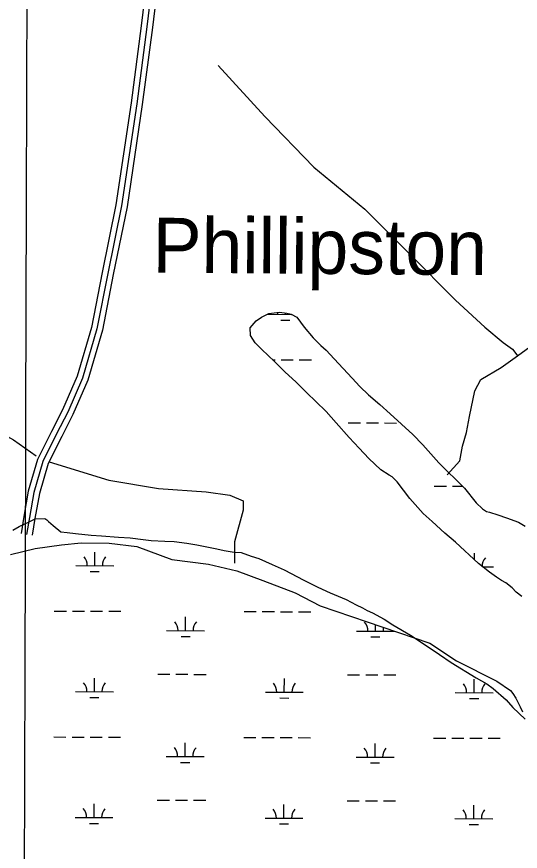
# Model space of a CAD drawing. Extents: x 3161665 to 3199565, y 885729 to 911164.
# Drawn here: x 3171102 to 3172433, y 897608 to 899813 of the extents above; entities that cross this region are included whole.
import ezdxf

# ---------------------------------------------------------------- set-up
doc = ezdxf.new("R2010")
doc.units = 0
for name, color, linetype in [('V-GRID-MAJR', 7, 'Continuous'), ('V-ROAD-CNTR', 7, 'Continuous'), ('V-SITE-VEGE', 7, 'Continuous'), ('V-TOPO-GNAM-IDEN', 7, 'Continuous'), ('V-TOPO-SHOR', 7, 'Continuous'), ('V-WETL-SWMP', 7, 'Continuous')]:
    doc.layers.add(name, color=color, linetype=linetype)

msp = doc.modelspace()

# ---------------------------------------------------------------- linework, layer by layer
at = {"layer": 'V-GRID-MAJR'}
msp.add_spline([(3171102.7, 891181.041), (3171121.2120000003, 897241.873), (3171139.73, 903304.649), (3171158.249, 909367.4720000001), (3171158.255, 909369.371)], degree=3, dxfattribs=at)
at = {"layer": 'V-ROAD-CNTR'}
for points in [[(3171451.753059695, 899962.9710463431), (3171430.6191019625, 899788.0113962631), (3171403.865155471, 899584.6108030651), (3171363.623235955, 899315.424341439), (3171327.398308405, 899136.9486983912), (3171298.884365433, 898991.522989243), (3171261.028441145, 898862.6312470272), (3171222.8165175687, 898774.211423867), (3171193.670575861, 898717.0455381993), (3171156.653649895, 898642.876686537), (3171132.1736988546, 898559.4978532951), (3171120.244722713, 898491.8829885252), (3171113.095737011, 898447.3320776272)], [(3171466.662029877, 899961.3150496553), (3171445.501072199, 899786.1334000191), (3171418.720125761, 899582.523807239), (3171378.401206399, 899312.8213466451), (3171342.108278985, 899134.013704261), (3171313.471336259, 898987.958996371), (3171275.161412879, 898857.5232572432), (3171236.396490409, 898767.8234366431), (3171207.063549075, 898710.2895517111), (3171170.670621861, 898637.3716975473), (3171146.8006696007, 898556.071860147), (3171135.0366931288, 898489.3919935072), (3171127.906707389, 898444.9560823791)], [(3171481.5710000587, 899959.6590529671), (3171460.3830424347, 899784.2554037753), (3171433.5750960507, 899580.436811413), (3171393.179176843, 899310.218351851), (3171356.8182495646, 899131.0787101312), (3171328.0583070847, 898984.395003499), (3171289.2943846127, 898852.4152674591), (3171249.976463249, 898761.4354494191), (3171220.4565222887, 898703.5335652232), (3171184.687593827, 898631.8667085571), (3171161.427640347, 898552.6458669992), (3171149.8286635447, 898486.9009984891), (3171142.717677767, 898442.580087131)]]:
    msp.add_lwpolyline(points, dxfattribs=at)
at = {"layer": 'V-SITE-VEGE'}
msp.add_lwpolyline([(3171091.5900000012, 898456.6059999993), (3171108.480000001, 898466.0019999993), (3171134.598000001, 898478.5609999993), (3171149.958000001, 898486.3959999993), (3171176.181000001, 898486.6129999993), (3171180.834000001, 898483.5699999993), (3171185.497000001, 898478.9779999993), (3171197.926000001, 898468.2839999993), (3171218.120000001, 898451.4839999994), (3171235.098000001, 898450.0789999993), (3171256.716000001, 898447.1749999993), (3171298.399000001, 898442.8949999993), (3171326.176000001, 898441.5799999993), (3171370.945000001, 898437.3219999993), (3171401.807000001, 898436.0359999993), (3171435.777000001, 898431.6899999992), (3171457.396000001, 898428.7839999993), (3171492.883000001, 898427.5349999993), (3171517.576000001, 898426.1969999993), (3171551.546000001, 898421.8489999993), (3171577.806000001, 898417.4399999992), (3171608.706000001, 898411.5249999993), (3171630.337000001, 898407.0769999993), (3171650.4280000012, 898402.6169999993), (3171676.687000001, 898398.2049999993), (3171695.207000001, 898396.8169999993), (3171721.508000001, 898387.7789999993), (3171741.609000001, 898381.7739999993), (3171777.224000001, 898365.1009999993), (3171808.187000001, 898351.4759999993), (3171860.856000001, 898324.1449999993), (3171898.029000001, 898305.9449999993), (3171930.549000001, 898290.7879999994), (3171972.347000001, 898272.6239999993), (3171998.682000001, 898258.9619999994), (3172015.711000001, 898251.3839999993), (3172028.116000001, 898243.7779999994), (3172042.048000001, 898237.7239999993), (3172073.037000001, 898221.0099999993), (3172096.300000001, 898205.7789999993), (3172142.802000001, 898178.3979999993), (3172173.817000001, 898158.6019999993), (3172218.801000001, 898128.1229999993), (3172249.828000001, 898106.7869999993), (3172316.497000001, 898065.6899999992), (3172344.386000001, 898050.4959999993), (3172361.457000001, 898038.2959999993), (3172395.6440000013, 898007.7289999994), (3172412.775000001, 897987.8189999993), (3172445.423000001, 897957.2379999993)], dxfattribs=at)
at = {"layer": 'V-TOPO-SHOR'}
for points in [[(3171633.7276054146, 899683.8705969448), (3171757.827883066, 899548.5373845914), (3171887.263373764, 899414.9695555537), (3172022.080953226, 899304.4923367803), (3172139.1118849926, 899186.9457721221), (3172261.4624045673, 899064.0561817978), (3172339.4986509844, 898992.8002143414), (3172387.3905664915, 898951.8213923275), (3172412.2309348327, 898933.995681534), (3172426.4086897, 898916.1934085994)], [(3172239.121537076, 898602.0564736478), (3172272.9685122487, 898639.3014009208), (3172280.1628600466, 898678.3820250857), (3172290.903599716, 898713.90063214), (3172298.1057601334, 898756.5354607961), (3172312.47101787, 898824.0340956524), (3172328.5313453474, 898854.2096770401), (3172381.9147262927, 898886.0803281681), (3172406.8332208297, 898903.7966622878), (3172419.2924680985, 898912.6548293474), (3172454.8892013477, 898937.4561345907), (3172485.150721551, 898960.4920565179), (3172510.069216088, 898978.2083906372), (3172542.0883069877, 898992.3548950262), (3172575.8805938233, 899004.7203908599), (3172595.4482500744, 899013.5629326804), (3172615.0159063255, 899022.405474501), (3172615.0159063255, 899022.405474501)], [(3170261.761000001, 898924.8649999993), (3170329.4202272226, 898917.248649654), (3170444.8889037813, 898897.446614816), (3170535.4781489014, 898877.6992683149), (3170690.019637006, 898847.1486811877), (3170823.212460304, 898805.9823563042), (3170917.332472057, 898775.5645837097), (3171030.9654517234, 898729.109921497), (3171093.089810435, 898695.2082579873), (3171153.4175353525, 898652.4249895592)], [(3171187.147321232, 898636.3568494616), (3171345.203950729, 898588.0274272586), (3171476.6626411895, 898566.4131333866), (3171602.8173690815, 898557.2502741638), (3171664.99641613, 898548.2280420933), (3171700.507210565, 898533.9330979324), (3171700.452522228, 898509.0536664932), (3171677.166596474, 898425.5806429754), (3171677.0415945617, 898368.7133711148)]]:
    msp.add_lwpolyline(points, dxfattribs=at)
at = {"layer": 'V-WETL-SWMP'}
for p, q in [((3171763.920245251, 899026.4123794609), (3171828.2566643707, 899026.234588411)), ((3171811.712233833, 899026.280308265), (3171811.7231690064, 899030.2373684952)), ((3171799.669636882, 899010.8825285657), (3171823.6695452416, 899010.8162058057)), ((3171777.977275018, 898906.3020749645), (3171784.536526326, 898906.2839487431)), ((3171800.5364652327, 898906.2397335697), (3171832.536343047, 898906.1513032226)), ((3171848.5362819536, 898906.1070880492), (3171880.536159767, 898906.0186577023)), ((3171977.984572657, 898739.5747285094), (3172009.9844504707, 898739.4862981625)), ((3172025.984389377, 898739.4420829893), (3172057.98426719, 898739.353652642)), ((3172073.9842060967, 898739.3094374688), (3172105.9840839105, 898739.2210071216)), ((3172205.523585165, 898572.444298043), (3172237.5234629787, 898572.3558676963)), ((3172253.5234018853, 898572.3116525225), (3172280.083977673, 898572.2382534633)), ((3171307.971383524, 898362.3200874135), (3171308.0708592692, 898398.319946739)), ((3172311.829225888, 898377.4831044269), (3172311.879141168, 898395.545714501)), ((3171257.9715819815, 898362.4582598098), (3171357.9711850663, 898362.181915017)), ((3172332.8352927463, 898359.4876655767), (3172361.779466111, 898359.4076795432)), ((3171295.9287919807, 898346.9223090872), (3171319.928696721, 898346.8559863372)), ((3171200.7960255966, 898242.5448144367), (3171232.795898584, 898242.456384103)), ((3171248.7958350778, 898242.4121689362), (3171280.795708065, 898242.3237386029)), ((3171296.7956445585, 898242.2795234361), (3171328.7955175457, 898242.1910931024)), ((3171344.7954540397, 898242.1468779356), (3171376.7953270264, 898242.0584476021)), ((3171547.970435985, 898190.8432230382), (3171548.0699117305, 898226.8430823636)), ((3171702.7020334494, 898241.1578178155), (3171734.701906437, 898241.0693874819)), ((3171750.70184293, 898241.0251723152), (3171782.701715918, 898240.9367419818)), ((3171798.7016524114, 898240.892526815), (3171830.7015253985, 898240.8040964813)), ((3171846.701461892, 898240.7598813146), (3171878.7013348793, 898240.6714509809)), ((3172049.8764438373, 898189.4562264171), (3172049.923488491, 898206.481491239)), ((3171497.9706344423, 898190.9813954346), (3171597.970237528, 898190.705050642)), ((3171999.876642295, 898189.5943988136), (3172099.8762453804, 898189.3180540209)), ((3171535.9278444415, 898175.4454447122), (3171559.9277491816, 898175.3791219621)), ((3172037.833852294, 898174.058448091), (3172061.8337570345, 898173.992125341)), ((3171474.2437639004, 898075.6145332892), (3171506.243636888, 898075.5261029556)), ((3171522.2435733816, 898075.4818877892), (3171554.2434463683, 898075.3934574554)), ((3171570.2433828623, 898075.3492422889), (3171602.2432558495, 898075.260811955)), ((3171976.1497717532, 898074.2275366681), (3172008.149644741, 898074.1391063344)), ((3172024.149581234, 898074.0948911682), (3172056.149454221, 898074.0064608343)), ((3172072.1493907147, 898073.9622456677), (3172104.149263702, 898073.8738153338)), ((3171307.052130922, 898029.6463873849), (3171307.1516066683, 898065.6462467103)), ((3171808.9581387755, 898028.2593907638), (3171809.057614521, 898064.2592500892)), ((3172310.864146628, 898026.8723941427), (3172310.9636223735, 898062.872253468)), ((3171257.05232938, 898029.7845597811), (3171357.0519324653, 898029.5082149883)), ((3171758.958337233, 898028.3975631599), (3171858.957940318, 898028.1212183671)), ((3171295.0095393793, 898014.2486090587), (3171319.0094441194, 898014.1822863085)), ((3171796.915547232, 898012.8616124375), (3171820.9154519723, 898012.7952896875)), ((3172260.864345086, 898027.0105665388), (3172360.8639481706, 898026.734221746)), ((3172298.8215550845, 898011.4746158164), (3172322.821459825, 898011.4082930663)), ((3171199.8767729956, 897909.871114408), (3171231.8766459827, 897909.7826840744)), ((3171247.876582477, 897909.7384689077), (3171279.876455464, 897909.6500385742)), ((3171295.8763919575, 897909.6058234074), (3171327.8762649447, 897909.5173930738)), ((3171343.8762014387, 897909.473177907), (3171375.876074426, 897909.3847475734)), ((3171701.7827808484, 897908.4841177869), (3171733.782653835, 897908.3956874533)), ((3171749.782590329, 897908.3514722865), (3171781.7824633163, 897908.2630419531)), ((3171797.78239981, 897908.2188267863), (3171829.7822727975, 897908.1303964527)), ((3171845.782209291, 897908.0861812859), (3171877.7820822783, 897907.9977509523)), ((3172203.6887887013, 897907.0971211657), (3172235.6886616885, 897907.0086908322)), ((3172251.6885981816, 897906.9644756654), (3172283.688471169, 897906.8760453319)), ((3172299.688407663, 897906.8318301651), (3172331.6882806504, 897906.7433998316)), ((3172347.6882171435, 897906.6991846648), (3172379.6880901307, 897906.6107543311)), ((3171547.0511833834, 897858.1695230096), (3171547.150659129, 897894.1693823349)), ((3172048.957191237, 897856.7825263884), (3172049.056666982, 897892.7823857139)), ((3171497.051381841, 897858.307695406), (3171597.0509849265, 897858.0313506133)), ((3171998.9573896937, 897856.9206987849), (3172098.9569927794, 897856.6443539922)), ((3171535.0085918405, 897842.7717446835), (3171559.0084965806, 897842.7054219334)), ((3172036.9145996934, 897841.3847480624), (3172060.914504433, 897841.3184253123)), ((3171473.3245112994, 897742.9408332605), (3171505.324384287, 897742.8524029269)), ((3171521.32432078, 897742.8081877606), (3171553.3241937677, 897742.7197574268)), ((3171569.324130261, 897742.6755422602), (3171601.3240032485, 897742.5871119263)), ((3171975.2305191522, 897741.5538366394), (3172007.2303921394, 897741.4654063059)), ((3172023.230328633, 897741.4211911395), (3172055.23020162, 897741.3327608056)), ((3172071.230138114, 897741.288545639), (3172103.230011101, 897741.2001153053)), ((3171306.1328783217, 897696.9726873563), (3171306.232354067, 897732.9725466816)), ((3171808.038886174, 897695.5856907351), (3171808.13836192, 897731.5855500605)), ((3172309.944894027, 897694.198694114), (3172310.0443697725, 897730.1985534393)), ((3171256.1330767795, 897697.1108597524), (3171356.132679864, 897696.8345149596)), ((3171294.0902867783, 897681.57490903), (3171318.090191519, 897681.5085862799)), ((3171758.039084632, 897695.7238631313), (3171858.038687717, 897695.4475183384)), ((3171795.996294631, 897680.1879124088), (3171819.9961993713, 897680.1215896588)), ((3172259.9450924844, 897694.3368665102), (3172359.9446955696, 897694.0605217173)), ((3172297.9023024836, 897678.8009157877), (3172321.902207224, 897678.7345930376))]:
    msp.add_line(p, q, dxfattribs=at)
for points in [[(3172436.668000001, 898280.9739999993), (3172422.069000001, 898292.7389999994), (3172411.2860000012, 898304.1659999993), (3172394.949000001, 898317.3149999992), (3172383.137000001, 898323.5349999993), (3172370.280000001, 898331.8339999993), (3172351.166000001, 898344.9779999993), (3172322.315000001, 898367.8149999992), (3172261.119000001, 898424.2389999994), (3172232.959000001, 898448.4659999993), (3172200.274000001, 898478.9289999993), (3172175.937000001, 898500.3879999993), (3172140.456000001, 898539.8669999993), (3172107.395000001, 898583.5149999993), (3172093.833000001, 898596.6699999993), (3172085.841000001, 898601.5099999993), (3172063.949000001, 898615.6879999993), (3172032.306000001, 898645.8069999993), (3172006.568000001, 898672.8149999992), (3171980.481000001, 898701.2099999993), (3171946.389000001, 898739.9979999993), (3171919.605000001, 898769.7799999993), (3171892.480000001, 898796.4379999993), (3171868.142000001, 898818.5919999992), (3171840.319000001, 898846.9829999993), (3171810.416000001, 898874.6759999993), (3171783.292000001, 898901.3349999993), (3171749.216000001, 898933.1819999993), (3171732.173000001, 898951.1879999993), (3171719.986000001, 898970.2459999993), (3171718.899000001, 898991.0629999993), (3171734.474000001, 899008.7939999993), (3171748.6780000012, 899018.8879999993), (3171767.742000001, 899028.2989999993), (3171796.187000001, 899032.1799999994), (3171815.277000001, 899029.7929999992), (3171827.4280000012, 899026.6969999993), (3171841.673000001, 899018.7479999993), (3171861.856000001, 898992.7679999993), (3171885.515000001, 898964.0199999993), (3171905.338000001, 898944.2859999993), (3171919.246000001, 898931.4779999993), (3171941.156000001, 898908.9719999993), (3171988.115000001, 898857.3739999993), (3172008.289000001, 898835.5579999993), (3172031.934000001, 898813.4029999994), (3172061.137000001, 898788.1379999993), (3172088.603000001, 898763.9089999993), (3172148.755000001, 898709.2179999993), (3172175.535000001, 898681.5179999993), (3172203.017000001, 898650.0019999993), (3172217.625000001, 898634.4199999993), (3172285.439000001, 898566.9069999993), (3172316.407000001, 898528.1129999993), (3172332.750000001, 898512.8809999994), (3172343.870000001, 898505.2719999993), (3172351.508000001, 898503.5539999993), (3172373.385000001, 898496.3159999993), (3172396.304000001, 898488.3859999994), (3172427.905000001, 898477.0049999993), (3172445.277000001, 898466.9809999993)], [(3171084.935000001, 898391.6679999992), (3171149.973000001, 898407.7949999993), (3171219.593000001, 898417.0829999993), (3171272.096000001, 898422.9079999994), (3171346.305000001, 898421.9309999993), (3171419.391000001, 898412.9599999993), (3171511.940000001, 898378.9159999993), (3171609.008000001, 898366.5729999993), (3171683.255000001, 898348.4719999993), (3171751.809000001, 898323.5069999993), (3171837.506000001, 898290.5899999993), (3171903.798000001, 898256.4869999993), (3172193.611000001, 898157.3079999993), (3172264.412000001, 898110.8999999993), (3172370.906000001, 898057.1709999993), (3172407.321000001, 898032.7889999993), (3172413.284000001, 898024.3369999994), (3172420.762000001, 898012.0819999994), (3172432.554000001, 897989.1779999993), (3172438.890000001, 897976.4879999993)]]:
    msp.add_lwpolyline(points, dxfattribs=at)
for centre, radius, start, end in [((3171756.47082076, 899026.9077706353), 35.24628790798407, 359.0698458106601, 7.533273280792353), ((3171252.7299786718, 898362.9475497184), 35.24628790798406, 359.06984576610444, 40.61350409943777), ((3171363.215412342, 898362.6422277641), 35.246287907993, 139.06984285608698, 180.6135011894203), ((3172367.0236942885, 898359.8679923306), 35.24628790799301, 139.06984280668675, 179.26079264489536), ((3171492.7290311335, 898191.4706853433), 35.24628790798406, 359.06984576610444, 40.61350409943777), ((3171603.214464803, 898191.1653633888), 35.246287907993, 139.06984285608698, 180.6135011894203), ((3171994.635038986, 898190.0836887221), 35.24628790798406, 359.06984576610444, 40.61350409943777), ((3172105.1204726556, 898189.7783667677), 35.246287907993, 164.4725740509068, 180.6135011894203), ((3171251.8107260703, 898030.2738496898), 35.24628790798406, 359.06984576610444, 40.61350409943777), ((3171362.2961597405, 898029.9685277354), 35.246287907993, 139.06984285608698, 180.6135011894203), ((3171753.716733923, 898028.8868530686), 35.24628790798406, 359.06984576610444, 40.61350409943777), ((3171864.2021675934, 898028.5815311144), 35.246287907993, 139.06984285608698, 180.6135011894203), ((3172255.622741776, 898027.4998564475), 35.24628790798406, 359.06984576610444, 40.61350409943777), ((3172366.1081754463, 898027.1945344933), 35.246287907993, 139.06984285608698, 180.6135011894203), ((3171491.809778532, 897858.7969853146), 35.24628790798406, 359.06984576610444, 40.61350409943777), ((3171602.2952122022, 897858.4916633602), 35.246287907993, 139.06984285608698, 180.6135011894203), ((3171993.7157863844, 897857.4099886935), 35.24628790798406, 359.06984576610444, 40.61350409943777), ((3172104.2012200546, 897857.104666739), 35.246287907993, 139.06984285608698, 180.6135011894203), ((3171250.89147347, 897697.6001496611), 35.24628790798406, 359.06984576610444, 40.61350409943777), ((3171361.37690714, 897697.2948277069), 35.246287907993, 139.06984285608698, 180.6135011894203), ((3171752.797481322, 897696.2131530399), 35.24628790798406, 359.06984576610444, 40.61350409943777), ((3171863.2829149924, 897695.9078310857), 35.246287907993, 139.06984285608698, 180.6135011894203), ((3172254.703489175, 897694.8261564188), 35.24628790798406, 359.06984576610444, 40.61350409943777), ((3172365.188922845, 897694.5208344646), 35.246287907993, 139.06984285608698, 180.6135011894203)]:
    msp.add_arc(centre, radius, start, end, dxfattribs=at)

# ---------------------------------------------------------------- texts
at = {"layer": 'V-TOPO-GNAM-IDEN'}
msp.add_text('Phillipston', height=144.99971199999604, rotation=359.5660400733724, dxfattribs=at).set_placement((3171460.3989513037, 899136.6351307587))

doc.saveas('drawing.dxf')
